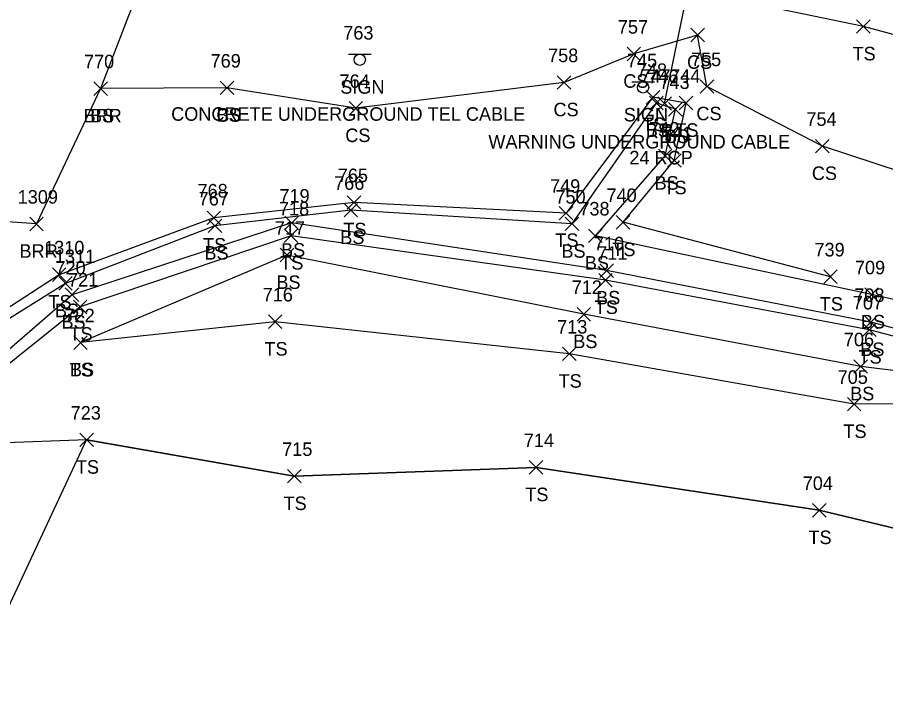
# Model space of a CAD drawing. Extents: x 1599569 to 1610055, y 642560 to 647860.
# Drawn here: x 1602520.1 to 1602648.3, y 647392.9 to 647493.1 of the extents above; entities that cross this region are included whole.
import ezdxf

# ---------------------------------------------------------------- set-up
doc = ezdxf.new("R2010")
doc.units = 0
for name, color, linetype in [('D_A', 7, 'Continuous'), ('D_C', 7, 'Continuous'), ('D_I', 7, 'Continuous'), ('D_TIC', 7, 'Continuous'), ('DCP', 7, 'Continuous'), ('L_A', 7, 'Continuous'), ('L_I', 7, 'Continuous'), ('L_TIC', 7, 'Continuous'), ('LABL', 7, 'Continuous'), ('LELB', 7, 'Continuous'), ('LSOGP', 7, 'Continuous'), ('S_A', 7, 'Continuous'), ('S_C', 7, 'Continuous'), ('S_I', 7, 'Continuous'), ('SSGN', 7, 'Continuous')]:
    doc.layers.add(name, color=color, linetype=linetype)

msp = doc.modelspace()

# ---------------------------------------------------------------- linework, layer by layer
at = {"layer": 'D_TIC'}
for points in [[(1602614.7, 647479.37), (1602616.7, 647481.37)], [(1602616.7, 647479.37), (1602614.7, 647481.37)]]:
    msp.add_lwpolyline(points, dxfattribs=at)
at = {"layer": 'DCP'}
msp.add_lwpolyline([(1602615.7, 647480.37), (1602628.4, 647541.89)], dxfattribs=at)
at = {"layer": 'L_TIC'}
for points in [[(1602644.06, 647490.74), (1602646.06, 647492.74)], [(1602646.06, 647490.74), (1602644.06, 647492.74)], [(1602619.57, 647489.49), (1602621.57, 647491.49)], [(1602621.57, 647489.49), (1602619.57, 647491.49)], [(1602610.15, 647486.69), (1602612.15, 647488.69)], [(1602612.15, 647486.69), (1602610.15, 647488.69)], [(1602599.84, 647482.48), (1602601.84, 647484.48)], [(1602601.84, 647482.48), (1602599.84, 647484.48)], [(1602531.37, 647481.57), (1602533.37, 647483.57)], [(1602533.37, 647481.57), (1602531.37, 647483.57)], [(1602531.37, 647481.57), (1602533.37, 647483.57)], [(1602533.37, 647481.57), (1602531.37, 647483.57)], [(1602550.04, 647481.68), (1602552.04, 647483.68)], [(1602552.04, 647481.68), (1602550.04, 647483.68)], [(1602550.04, 647481.68), (1602552.04, 647483.68)], [(1602552.04, 647481.68), (1602550.04, 647483.68)], [(1602620.95, 647481.89), (1602622.95, 647483.89)], [(1602622.95, 647481.89), (1602620.95, 647483.89)], [(1602612.97, 647480.29), (1602614.97, 647482.29)], [(1602614.97, 647480.29), (1602612.97, 647482.29)], [(1602613.47, 647479.43), (1602615.47, 647481.43)], [(1602615.47, 647479.43), (1602613.47, 647481.43)], [(1602617.87, 647479.44), (1602619.87, 647481.44)], [(1602619.87, 647479.44), (1602617.87, 647481.44)], [(1602569.08, 647478.67), (1602571.08, 647480.67)], [(1602571.08, 647478.67), (1602569.08, 647480.67)], [(1602616.29, 647478.52), (1602618.29, 647480.52)], [(1602618.29, 647478.52), (1602616.29, 647480.52)], [(1602638.01, 647473.07), (1602640.01, 647475.07)], [(1602640.01, 647473.07), (1602638.01, 647475.07)], [(1602614.77, 647471.63), (1602616.77, 647473.63)], [(1602616.77, 647471.63), (1602614.77, 647473.63)], [(1602616.12, 647470.95), (1602618.12, 647472.95)], [(1602618.12, 647470.95), (1602616.12, 647472.95)], [(1602568.82, 647464.75), (1602570.82, 647466.75)], [(1602570.82, 647464.75), (1602568.82, 647466.75)], [(1602568.34, 647463.61), (1602570.34, 647465.61)], [(1602570.34, 647463.61), (1602568.34, 647465.61)], [(1602568.34, 647463.61), (1602570.34, 647465.61)], [(1602570.34, 647463.61), (1602568.34, 647465.61)], [(1602600.14, 647463.17), (1602602.14, 647465.17)], [(1602602.14, 647463.17), (1602600.14, 647465.17)], [(1602521.9, 647461.57), (1602523.9, 647463.57)], [(1602523.9, 647461.57), (1602521.9, 647463.57)], [(1602548.1, 647462.48), (1602550.1, 647464.48)], [(1602550.1, 647462.48), (1602548.1, 647464.48)], [(1602559.59, 647461.73), (1602561.59, 647463.73)], [(1602561.59, 647461.73), (1602559.59, 647463.73)], [(1602601, 647461.58), (1602603, 647463.58)], [(1602603, 647461.58), (1602601, 647463.58)], [(1602608.56, 647461.81), (1602610.56, 647463.81)], [(1602610.56, 647461.81), (1602608.56, 647463.81)], [(1602548.27, 647461.3), (1602550.27, 647463.3)], [(1602550.27, 647461.3), (1602548.27, 647463.3)], [(1602559.51, 647459.83), (1602561.51, 647461.83)], [(1602561.51, 647459.83), (1602559.51, 647461.83)], [(1602604.47, 647459.82), (1602606.47, 647461.82)], [(1602606.47, 647459.82), (1602604.47, 647461.82)], [(1602558.9, 647456.97), (1602560.9, 647458.97)], [(1602560.9, 647456.97), (1602558.9, 647458.97)], [(1602525.25, 647454.07), (1602527.25, 647456.07)], [(1602527.25, 647454.07), (1602525.25, 647456.07)], [(1602606.13, 647454.67), (1602608.13, 647456.67)], [(1602608.13, 647454.67), (1602606.13, 647456.67)], [(1602639.21, 647453.77), (1602641.21, 647455.77)], [(1602641.21, 647453.77), (1602639.21, 647455.77)], [(1602526.18, 647452.79), (1602528.18, 647454.79)], [(1602528.18, 647452.79), (1602526.18, 647454.79)], [(1602605.96, 647453.27), (1602607.96, 647455.27)], [(1602607.96, 647453.27), (1602605.96, 647455.27)], [(1602645.26, 647451.13), (1602647.26, 647453.13)], [(1602647.26, 647451.13), (1602645.26, 647453.13)], [(1602527.15, 647451.11), (1602529.15, 647453.11)], [(1602529.15, 647451.11), (1602527.15, 647453.11)], [(1602528.36, 647449.31), (1602530.36, 647451.31)], [(1602530.36, 647449.31), (1602528.36, 647451.31)], [(1602602.76, 647448.22), (1602604.76, 647450.22)], [(1602604.76, 647448.22), (1602602.76, 647450.22)], [(1602557.17, 647447.12), (1602559.17, 647449.12)], [(1602559.17, 647447.12), (1602557.17, 647449.12)], [(1602645.16, 647447.05), (1602647.16, 647449.05)], [(1602647.16, 647447.05), (1602645.16, 647449.05)], [(1602644.94, 647445.93), (1602646.94, 647447.93)], [(1602646.94, 647445.93), (1602644.94, 647447.93)], [(1602528.4, 647444.04), (1602530.4, 647446.04)], [(1602530.4, 647444.04), (1602528.4, 647446.04)], [(1602528.4, 647444.04), (1602530.4, 647446.04)], [(1602530.4, 647444.04), (1602528.4, 647446.04)], [(1602600.62, 647442.37), (1602602.62, 647444.37)], [(1602602.62, 647442.37), (1602600.62, 647444.37)], [(1602643.67, 647440.5), (1602645.67, 647442.5)], [(1602645.67, 647440.5), (1602643.67, 647442.5)], [(1602642.7, 647434.94), (1602644.7, 647436.94)], [(1602644.7, 647434.94), (1602642.7, 647436.94)], [(1602529.32, 647429.66), (1602531.32, 647431.66)], [(1602531.32, 647429.66), (1602529.32, 647431.66)], [(1602595.7, 647425.6), (1602597.7, 647427.6)], [(1602597.7, 647425.6), (1602595.7, 647427.6)], [(1602559.99, 647424.29), (1602561.99, 647426.29)], [(1602561.99, 647424.29), (1602559.99, 647426.29)], [(1602637.54, 647419.26), (1602639.54, 647421.26)], [(1602639.54, 647419.26), (1602637.54, 647421.26)]]:
    msp.add_lwpolyline(points, dxfattribs=at)
at = {"layer": 'LABL'}
msp.add_lwpolyline([(1602538.93, 647499.63), (1602532.37, 647482.57), (1602522.9, 647462.57), (1602503.46, 647463.92)], dxfattribs=at)
at = {"layer": 'LELB'}
for points in [[(1602920.15, 647395.93), (1602878.36, 647413), (1602839.66, 647426.29), (1602797.14, 647444.47), (1602757.03, 647458.46), (1602729.83, 647462.67), (1602705.16, 647473.23), (1602676.17, 647483.37), (1602645.06, 647491.74), (1602608.39, 647499.39), (1602581.9, 647503.71), (1602538.18, 647509.07), (1602515.71, 647510.39), (1602496.95, 647511.81), (1602468.81, 647510.52), (1602437.53, 647504.14), (1602407.66, 647504.45), (1602378.45, 647504.43), (1602350.14, 647499.82), (1602309.52, 647489.18), (1602272.83, 647479.89), (1602236.83, 647468.86)], [(1602844.82, 647413.51), (1602810.8, 647429.9), (1602787.42, 647437.73), (1602740.96, 647454.08), (1602700.04, 647463.04), (1602670.27, 647463.75), (1602639.01, 647474.07), (1602621.95, 647482.89), (1602620.57, 647490.49), (1602611.15, 647487.69), (1602600.84, 647483.48), (1602570.08, 647479.67), (1602551.04, 647482.68)], [(1602640.21, 647454.77), (1602609.56, 647462.81), (1602617.12, 647471.95), (1602618.87, 647480.44), (1602613.97, 647481.29), (1602601.14, 647464.17), (1602569.82, 647465.75), (1602549.1, 647463.48), (1602526.25, 647455.07), (1602511.13, 647445.27), (1602505.22, 647440.37), (1602505.06, 647452.95), (1602503.46, 647463.92), (1602499.61, 647484.09), (1602493.9, 647482.98), (1602495.14, 647473.06), (1602496.95, 647464.06), (1602499.78, 647448.52), (1602500.13, 647429.64), (1602491.84, 647404.46), (1602487.58, 647376.38), (1602484.88, 647364.35)], [(1602569.34, 647464.61), (1602549.27, 647462.3), (1602527.18, 647453.79), (1602511.78, 647444.16), (1602504.08, 647438.52), (1602503.89, 647453.25), (1602501.73, 647463.87), (1602498.92, 647483.55), (1602495.09, 647483.03), (1602498.76, 647464.83), (1602500.74, 647448.31), (1602501.22, 647429.33), (1602492.6, 647403.99), (1602488.17, 647376.23), (1602485.85, 647364.3)], [(1602551.04, 647482.68), (1602532.37, 647482.57)], [(1603012.49, 647326.24), (1602990.45, 647341.3), (1602973.77, 647353.11), (1602953.95, 647363.4), (1602916.83, 647376.34), (1602879.52, 647385.68), (1602861.45, 647391.05), (1602857.96, 647395.91), (1602856.57, 647396.23), (1602848.89, 647379.86), (1602843.21, 647377.7), (1602818.67, 647385.57), (1602771.25, 647404.63), (1602731.78, 647425.59), (1602689.48, 647442.33), (1602646.26, 647452.13), (1602605.47, 647460.82), (1602615.77, 647472.63), (1602617.29, 647479.52), (1602614.47, 647480.43), (1602602, 647462.58), (1602569.34, 647464.61)], [(1602941.78, 647364.94), (1602916.7, 647374.33), (1602878.74, 647383.8), (1602864.18, 647385.07), (1602847.83, 647371.45), (1602840.84, 647371.94), (1602817.04, 647381.69), (1602769.81, 647402.39), (1602730.45, 647422.72), (1602686.99, 647437.34), (1602646.16, 647448.05), (1602607.13, 647455.67), (1602560.59, 647462.73), (1602528.15, 647452.11), (1602504.4, 647431.52), (1602495.06, 647409.31), (1602489.51, 647381.97), (1602486.55, 647364.53)], [(1602941.34, 647363.29), (1602915.67, 647371.75), (1602877.66, 647379.52), (1602865.48, 647379.11), (1602848.78, 647367.3), (1602839.38, 647367.46), (1602815.63, 647378.56), (1602768.2, 647398.54), (1602730, 647421.7), (1602686.76, 647436.3), (1602645.94, 647446.93), (1602606.96, 647454.27), (1602560.51, 647460.83), (1602529.36, 647450.31), (1602505.68, 647431.34)], [(1602686.76, 647436.3), (1602644.67, 647441.5), (1602603.76, 647449.22), (1602559.9, 647457.97), (1602529.4, 647445.04)], [(1602686.76, 647436.3), (1602643.7, 647435.94), (1602601.62, 647443.37), (1602558.17, 647448.12), (1602529.4, 647445.04)], [(1602839.57, 647352.07), (1602813.03, 647373.12), (1602764.75, 647390.08), (1602724.91, 647402.52), (1602674.58, 647411.62), (1602638.54, 647420.26), (1602596.7, 647426.6), (1602560.99, 647425.29), (1602530.32, 647430.66), (1602507.69, 647429.82), (1602506.13, 647378.88), (1602501.5, 647362.17)]]:
    msp.add_lwpolyline(points, dxfattribs=at)
at = {"layer": 'LSOGP'}
msp.add_lwpolyline([(1602254.53, 647178.83), (1602291.22, 647199.13), (1602313.63, 647215.92), (1602341.47, 647237.55), (1602366.54, 647253.73), (1602389.31, 647268.29), (1602449.83, 647301.87), (1602453.66, 647307.87), (1602460.55, 647316.67), (1602462.33, 647322.8), (1602472.93, 647343.79), (1602485.85, 647364.3), (1602486.56, 647364.52), (1602487.54, 647364.39), (1602501.5, 647362.17), (1602506.13, 647378.88), (1602530.31, 647430.66), (1602560.99, 647425.29), (1602596.7, 647426.6), (1602638.54, 647420.26), (1602674.58, 647411.62)], dxfattribs=at)
at = {"layer": 'SSGN'}
for p, q in [((1602569, 647487.68), (1602572.33, 647487.68)), ((1602570.65, 647486.84), (1602570.65, 647486.84)), ((1602610.87, 647483.58), (1602614.21, 647483.58)), ((1602612.52, 647482.75), (1602612.52, 647482.75))]:
    msp.add_line(p, q, dxfattribs=at)
for centre in [(1602570.65, 647486.84), (1602612.52, 647482.75)]:
    msp.add_circle(centre, 0.833, dxfattribs=at)

# ---------------------------------------------------------------- texts
at = {"layer": 'D_A'}
msp.add_text('P', height=2, dxfattribs=at).set_placement((1602615.08, 647475.37))
at = {"layer": 'D_C'}
msp.add_text('24 RCP', height=2, dxfattribs=at).set_placement((1602610.49, 647471.37))
at = {"layer": 'D_I'}
msp.add_text('746', height=2, dxfattribs=at).set_placement((1602613.28, 647483.37))
at = {"layer": 'L_A'}
for s, p in [('TS', (1602643.46, 647486.74)), ('CS', (1602619.01, 647485.49)), ('CS', (1602609.59, 647482.69)), ('CS', (1602599.28, 647478.48)), ('BRR', (1602529.85, 647477.57)), ('BS', (1602530.81, 647477.57)), ('CS', (1602549.48, 647477.68)), ('BS', (1602549.48, 647477.68)), ('CS', (1602620.39, 647477.89)), ('TS', (1602612.38, 647476.29)), ('CS', (1602568.52, 647474.67)), ('BS', (1602612.91, 647475.43)), ('BS', (1602615.73, 647474.52)), ('TS', (1602617.28, 647475.44)), ('CS', (1602637.45, 647469.07)), ('BS', (1602614.21, 647467.63)), ('TS', (1602615.53, 647466.95)), ('TS', (1602568.23, 647460.75)), ('BS', (1602567.78, 647459.61)), ('BS', (1602567.78, 647459.61)), ('TS', (1602599.55, 647459.17)), ('BRR', (1602520.39, 647457.57)), ('TS', (1602547.51, 647458.48)), ('BS', (1602559.03, 647457.73)), ('BS', (1602600.45, 647457.58)), ('TS', (1602607.97, 647457.81)), ('BS', (1602547.71, 647457.3)), ('TS', (1602558.92, 647455.83)), ('BS', (1602603.91, 647455.82)), ('BS', (1602558.34, 647452.97)), ('TS', (1602524.66, 647450.07)), ('BS', (1602605.57, 647450.67)), ('BS', (1602525.62, 647448.79)), ('TS', (1602605.37, 647449.27)), ('TS', (1602638.62, 647449.77)), ('BS', (1602526.59, 647447.11)), ('BS', (1602644.7, 647447.13)), ('TS', (1602527.77, 647445.31)), ('BS', (1602602.2, 647444.22)), ('TS', (1602556.58, 647443.12)), ('BS', (1602644.6, 647443.05)), ('TS', (1602644.35, 647441.93)), ('TS', (1602527.81, 647440.04)), ('BS', (1602527.84, 647440.04)), ('TS', (1602600.03, 647438.37)), ('BS', (1602643.11, 647436.5)), ('TS', (1602642.11, 647430.94)), ('TS', (1602528.72, 647425.66)), ('TS', (1602595.11, 647421.6)), ('TS', (1602559.4, 647420.29)), ('TS', (1602636.95, 647415.26))]:
    msp.add_text(s, height=2, dxfattribs=at).set_placement(p)
at = {"layer": 'L_I'}
for s, p in [('757', (1602608.79, 647490.69)), ('758', (1602598.48, 647486.48)), ('755', (1602619.59, 647485.89)), ('770', (1602529.92, 647485.57)), ('770', (1602529.92, 647485.57)), ('769', (1602548.62, 647485.68)), ('769', (1602548.62, 647485.68)), ('748', (1602611.6, 647484.29)), ('747', (1602612.11, 647483.43)), ('744', (1602616.51, 647483.44)), ('764', (1602567.67, 647482.67)), ('743', (1602614.93, 647482.52)), ('754', (1602636.64, 647477.07)), ('742', (1602613.41, 647475.63)), ('741', (1602615.33, 647474.95)), ('765', (1602567.41, 647468.75)), ('768', (1602546.69, 647466.48)), ('766', (1602566.87, 647467.61)), ('766', (1602566.87, 647467.61)), ('749', (1602598.77, 647467.17)), ('1309', (1602520.12, 647465.57)), ('767', (1602546.86, 647465.3)), ('719', (1602558.79, 647465.73)), ('750', (1602599.56, 647465.58)), ('740', (1602607.11, 647465.81)), ('718', (1602558.72, 647463.83)), ('738', (1602603.1, 647463.82)), ('717', (1602558.11, 647460.97)), ('1310', (1602524.03, 647458.07)), ('710', (1602605.25, 647458.67)), ('739', (1602637.84, 647457.77)), ('1311', (1602525.62, 647456.79)), ('711', (1602605.74, 647457.27)), ('720', (1602525.7, 647455.11)), ('709', (1602643.81, 647455.13)), ('721', (1602527.56, 647453.31)), ('716', (1602556.32, 647451.12)), ('712', (1602601.97, 647452.22)), ('707', (1602643.5, 647449.93)), ('708', (1602643.72, 647451.05)), ('722', (1602527.04, 647448.04)), ('722', (1602527.04, 647448.04)), ('713', (1602599.82, 647446.37)), ('706', (1602642.17, 647444.5)), ('705', (1602641.26, 647438.94)), ('723', (1602527.95, 647433.66)), ('714', (1602594.9, 647429.6)), ('715', (1602559.2, 647428.29)), ('704', (1602636.1, 647423.26))]:
    msp.add_text(s, height=2, dxfattribs=at).set_placement(p)
at = {"layer": 'S_A'}
for p in [(1602567.78, 647481.82), (1602609.66, 647477.72)]:
    msp.add_text('SIGN', height=2, dxfattribs=at).set_placement(p)
at = {"layer": 'S_C'}
for s, p in [('CONCRETE UNDERGROUND TEL CABLE', (1602542.8, 647477.82)), ('WARNING UNDERGROUND CABLE', (1602589.66, 647473.72))]:
    msp.add_text(s, height=2, dxfattribs=at).set_placement(p)
at = {"layer": 'S_I'}
for s, p in [('763', (1602568.22, 647489.82)), ('745', (1602610.14, 647485.72))]:
    msp.add_text(s, height=2, dxfattribs=at).set_placement(p)

doc.saveas('drawing.dxf')
